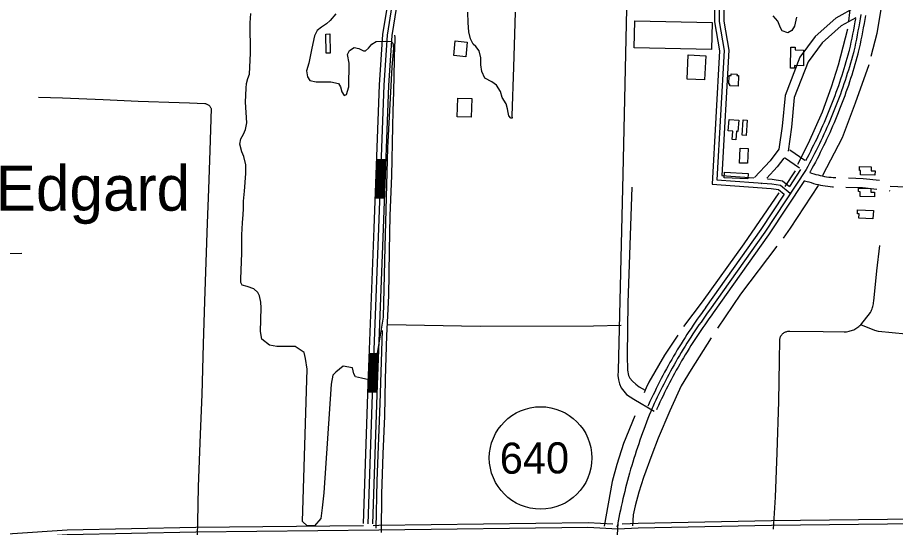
# Model space of a CAD drawing. Extents: x 3508733 to 3546731, y 546897 to 572481.
# Drawn here: x 3524246 to 3527070, y 560221 to 561862 of the extents above; entities that cross this region are included whole.
import ezdxf

# ---------------------------------------------------------------- set-up
doc = ezdxf.new("R2010")
doc.units = 0
for name, color, linetype in [('V-BLDG-OTLN', 7, 'Continuous'), ('V-DTCH-CNTR', 7, 'Continuous'), ('V-ROAD-CNTR', 7, 'Continuous'), ('V-ROAD-IDEN', 7, 'Continuous'), ('V-SITE-VEGE', 7, 'Continuous'), ('V-TOPO-GNAM-IDEN', 7, 'Continuous'), ('V-TOPO-SHOR', 7, 'Continuous')]:
    doc.layers.add(name, color=color, linetype=linetype)

msp = doc.modelspace()

# ---------------------------------------------------------------- linework, layer by layer
at = {"layer": 'V-BLDG-OTLN'}
for points in [[(3526478.2, 561760.1), (3526229.7, 561764.8), (3526231.4, 561851.6), (3526479.8, 561846.8)], [(3525250.2, 561809.5), (3525250.9, 561747.8), (3525238.4, 561747.7), (3525237.7, 561809.3)], [(3525688, 561736.2), (3525649, 561739.9), (3525653.5, 561787), (3525692.5, 561783.3)], [(3526732.8, 561699.1), (3526733.7, 561767.4), (3526747.8, 561767.2), (3526747.7, 561758.3), (3526774.4, 561757.9), (3526773.7, 561707.4), (3526745.4, 561707.7), (3526745.3, 561699)], [(3526399.4, 561664.1), (3526403, 561741.9), (3526459.7, 561739.2), (3526456.1, 561661.5)], [(3526533.9, 561648), (3526534.7, 561676), (3526541.6, 561675.8), (3526541.7, 561680.8), (3526560.2, 561680.3), (3526560.1, 561675.8), (3526564.5, 561675.6), (3526563.6, 561641.7), (3526536.9, 561642.4), (3526537, 561648)], [(3525706.9, 561601.4), (3525705.3, 561541.6), (3525660.4, 561542.8), (3525662, 561602.6)], [(3526558.8, 561496.2), (3526556.5, 561469.3), (3526544.3, 561470.3), (3526546.6, 561496.6), (3526532.2, 561497.9), (3526535.3, 561534.2), (3526565.7, 561531.6), (3526562.6, 561495.8)], [(3526592.8, 561532.5), (3526590, 561483), (3526576.8, 561483.8), (3526579.7, 561533.3)], [(3526596.2, 561441.1), (3526594.4, 561393.2), (3526568.1, 561394.2), (3526569.9, 561442.1)], [(3527003.9, 561355), (3526957, 561356.7), (3526957.5, 561370.5), (3526953.8, 561370.6), (3526954.3, 561382.9), (3526991.9, 561381.5), (3526991.4, 561369.1), (3527004.4, 561368.7)], [(3526595.2, 561343.2), (3526519.1, 561346.8), (3526519.9, 561364.5), (3526596.1, 561360.9)], [(3527002.2, 561285.3), (3526956, 561286.5), (3526956.4, 561301.9), (3526950.6, 561302), (3526951, 561313.6), (3526990.7, 561312.5), (3526990.3, 561300.2), (3527002.6, 561299.9)], [(3526997.6, 561214.8), (3526952.5, 561216.8), (3526953.1, 561230.4), (3526947.4, 561230.7), (3526947.9, 561243.4), (3526998.8, 561241.2)]]:
    msp.add_lwpolyline(points, close=True, dxfattribs=at)
at = {"layer": 'V-DTCH-CNTR'}
for points in [[(3525416.9, 560204.7), (3525418.1, 560327.9), (3525422.3, 560458.3), (3525426.9, 560579.6), (3525429.4, 560698.6), (3525434.2, 560839.5), (3525439.6, 560966.8), (3525442.3, 561111.1), (3525444, 561225.7), (3525449.4, 561353), (3525452.6, 561511.7), (3525453.9, 561561.2), (3525455.8, 561623.5), (3525458.1, 561727.1), (3525459.9, 561774.5), (3525460.2, 561782.4), (3525460.2, 561790.4), (3525460.1, 561798.3), (3525459.7, 561806.2)], [(3524313.3, 561605.7), (3524390.6, 561604.4), (3524521.4, 561598.3), (3524633.5, 561593.6), (3524765.9, 561589.1), (3524798.6, 561588)], [(3524798.6, 561588), (3524848.1, 561585.9), (3524850.4, 561585.5), (3524852.6, 561584.8), (3524854.7, 561584), (3524856.8, 561583), (3524858.8, 561581.8), (3524860.6, 561580.4), (3524862.3, 561578.9), (3524863.9, 561577.2), (3524865.3, 561575.4), (3524866.5, 561573.4), (3524867.6, 561571.4), (3524868.5, 561569.3), (3524863.8, 561435), (3524859.7, 561310.2), (3524855.5, 561201.1), (3524851.6, 561075.5), (3524847.3, 560949.5), (3524843.1, 560811.6), (3524838.3, 560649.5), (3524833.4, 560521.9), (3524826.8, 560352.2), (3524824.4, 560238.5), (3524823.2, 560195.8)], [(3527053.2, 561320.1), (3527227.7, 561312.6)], [(3526677.9, 560215.7), (3526684.1, 560319.2), (3526689.9, 560461.6), (3526694.9, 560626.2), (3526696.5, 560757.4), (3526698, 560825.7), (3526698.3, 560828.2), (3526698.8, 560830.6), (3526699.5, 560833), (3526700.4, 560835.3), (3526701.6, 560837.5), (3526702.8, 560839.6), (3526704.3, 560841.6), (3526705.9, 560843.5), (3526707.7, 560845.2), (3526709.6, 560846.8), (3526711.7, 560848.2), (3526713.8, 560849.4), (3526716, 560850.5), (3526718.4, 560851.3), (3526720.7, 560852), (3526723.2, 560852.5), (3526725.6, 560852.7), (3526728.1, 560852.8), (3526730.6, 560852.6), (3526837.4, 560851.5), (3526905, 560850.8), (3526908.9, 560851), (3526912.9, 560851.3), (3526916.8, 560851.9), (3526920.6, 560852.7), (3526924.5, 560853.6), (3526928.3, 560854.8), (3526932, 560856.2), (3526935.6, 560857.7), (3526939.2, 560859.5), (3526942.6, 560861.4), (3526946, 560863.5), (3526949.2, 560865.8), (3526952.3, 560868.3), (3526955.3, 560870.9), (3526958.1, 560873.7), (3526989.3, 560913.2), (3526991.3, 560916.9), (3526993.1, 560920.8), (3526994.7, 560924.8), (3526996.1, 560928.8), (3526997.3, 560932.9), (3526998.3, 560937.1), (3526999.1, 560941.3), (3526999.6, 560945.5), (3527000, 560949.8), (3527010.5, 561047), (3527019.2, 561129.1)], [(3523718.4, 561092.1), (3523864.6, 561096.1), (3524003.1, 561100.4), (3524146.8, 561101.7), (3524259.5, 561104.1)], [(3525435.7, 560874.7), (3525734, 560868.9), (3526098.5, 560870.7), (3526187, 560872.6)], [(3527252.9, 560831.6), (3527147.3, 560839.5), (3527015.7, 560851.8), (3527003.4, 560854.7), (3526958.1, 560873.7)]]:
    msp.add_lwpolyline(points, dxfattribs=at)
at = {"layer": 'V-ROAD-CNTR'}
for p, q in [((3525430.2, 561404.9), (3525400.3, 561406)), ((3527050, 561305.3), (3527051.5, 561305.2)), ((3525425.6, 561280), (3525395.6, 561281.1)), ((3525406.1, 560780.4), (3525376.1, 560781.6)), ((3525401.3, 560655.6), (3525371.3, 560656.5))]:
    msp.add_line(p, q, dxfattribs=at)
for points in [[(3526491.5, 562227.9), (3526487.7, 561848.4), (3526504.1, 561755.6), (3526479.9, 561326.3), (3526670.3, 561312.4), (3526693.8, 561308.9), (3526712.1, 561293.8)], [(3526506.5, 562227.8), (3526502.7, 561849.6), (3526519.2, 561756.5), (3526495.7, 561340.2), (3526671.9, 561327.3), (3526700.2, 561323.1), (3526731, 561297.6)], [(3526521.5, 562227.6), (3526517.7, 561850.9), (3526534.3, 561757.4), (3526511.5, 561354), (3526614.1, 561346.5)], [(3525482.3, 562076.1), (3525460.2, 561988.9), (3525435.3, 561905), (3525420.2, 561807.5), (3525409.2, 561645.6), (3525392, 561184.9), (3525372.2, 560681.9), (3525357.6, 560233.9)], [(3525496.9, 562072.4), (3525474.6, 561985), (3525449.9, 561901.7), (3525435.2, 561805.8), (3525424.1, 561644.8), (3525407, 561184.4), (3525387.1, 560681.4), (3525372.6, 560233.4)], [(3525511.4, 562068.8), (3525489.1, 561981), (3525464.6, 561898.4), (3525450.1, 561804.2), (3525439.1, 561644), (3525422, 561183.8), (3525402.1, 560680.8), (3525387.6, 560232.9)], [(3526206.2, 561939.5), (3526193.4, 561358.8), (3526177.8, 560724.9)], [(3526944, 561896.4), (3526877.9, 561860.9), (3526811.7, 561801.2), (3526762.1, 561734.8), (3526714.7, 561611.5), (3526705.7, 561513.1), (3526695.2, 561438.9), (3526666.7, 561400.7), (3526616.3, 561347.6)], [(3526942.1, 561861.3), (3526895.3, 561836.2), (3526834, 561780.9), (3526788.6, 561720.1), (3526744.2, 561604.7), (3526735.5, 561509.7), (3526724.7, 561432.8)], [(3526958.7, 561871.8), (3526956.5, 561858.7), (3526954.2, 561845.6), (3526951.8, 561832.5), (3526949.3, 561819.4), (3526946.8, 561806.3), (3526944.1, 561793.2), (3526941.4, 561780.2), (3526938.7, 561767.2), (3526935.8, 561754.2), (3526934.6, 561748.8)], [(3526973.5, 561869.3), (3526971.3, 561856.1), (3526968.9, 561842.9), (3526966.5, 561829.7), (3526964, 561816.5), (3526961.5, 561803.4), (3526958.8, 561790.2), (3526956.1, 561777.1), (3526953.3, 561764), (3526950.4, 561750.9), (3526949.2, 561745.5)], [(3526941.2, 561858.4), (3526939.4, 561848.2), (3526937, 561835.2), (3526934.6, 561822.2), (3526932.1, 561809.2), (3526929.4, 561796.2), (3526926.8, 561783.3), (3526924, 561770.4), (3526921.2, 561757.4), (3526920, 561752.1)], [(3526920.1, 561752.7), (3526917.1, 561741.6), (3526913.9, 561730.5), (3526910.7, 561719.5), (3526907.5, 561708.4), (3526904.1, 561697.4), (3526900.7, 561686.5), (3526897.2, 561675.5), (3526893.6, 561664.6), (3526890, 561653.7), (3526886.2, 561642.8), (3526882.4, 561631.9), (3526878.6, 561621.1), (3526874.6, 561610.3), (3526870.6, 561599.5), (3526866.5, 561588.8), (3526862.3, 561578), (3526858.1, 561567.3), (3526853.7, 561556.7), (3526849.3, 561546.1), (3526844.9, 561535.4), (3526840.3, 561524.9), (3526835.7, 561514.3), (3526831, 561503.8), (3526826.3, 561493.4), (3526821.4, 561482.9), (3526816.5, 561472.5), (3526811.6, 561462.1), (3526806.5, 561451.8), (3526801.4, 561441.5), (3526796.2, 561431.2), (3526790.9, 561421), (3526785.6, 561410.8), (3526780.4, 561401)], [(3526934.6, 561748.8), (3526931.5, 561737.6), (3526928.4, 561726.4), (3526925.1, 561715.3), (3526921.8, 561704.1), (3526918.5, 561693), (3526915, 561681.9), (3526911.5, 561670.9), (3526907.9, 561659.9), (3526904.2, 561648.8), (3526900.4, 561637.9), (3526896.6, 561626.9), (3526892.7, 561616), (3526888.7, 561605.1), (3526884.6, 561594.2), (3526880.5, 561583.4), (3526876.3, 561572.5), (3526872, 561561.8), (3526867.6, 561551), (3526863.2, 561540.3), (3526858.7, 561529.6), (3526854.1, 561518.9), (3526849.4, 561508.3), (3526844.7, 561497.7), (3526839.9, 561487.1), (3526835, 561476.6), (3526830.1, 561466.1), (3526825.1, 561455.6), (3526820, 561445.2), (3526814.8, 561434.8), (3526809.6, 561424.4), (3526804.3, 561414.1), (3526798.9, 561403.8), (3526793.4, 561393.6), (3526787.9, 561383.3), (3526782.5, 561373.4)], [(3526949.1, 561744.8), (3526946, 561733.6), (3526942.8, 561722.3), (3526939.5, 561711), (3526936.2, 561699.8), (3526932.8, 561688.6), (3526929.3, 561677.4), (3526925.7, 561666.3), (3526922.1, 561655.1), (3526918.4, 561644), (3526914.6, 561633), (3526910.7, 561621.9), (3526906.8, 561610.9), (3526902.7, 561599.9), (3526898.6, 561588.9), (3526894.5, 561578), (3526890.2, 561567.1), (3526885.9, 561556.2), (3526881.5, 561545.3), (3526877, 561534.5), (3526872.5, 561523.7), (3526867.8, 561512.9), (3526863.2, 561502.2), (3526858.4, 561491.5), (3526853.5, 561480.9), (3526848.6, 561470.2), (3526843.6, 561459.6), (3526838.6, 561449.1), (3526833.4, 561438.5), (3526828.2, 561428.1), (3526822.9, 561417.6), (3526817.6, 561407.2), (3526812.2, 561396.8), (3526806.7, 561386.5), (3526801.1, 561376.2), (3526795.6, 561366.2)], [(3526710.9, 561409.8), (3526689.6, 561381.4), (3526655.6, 561345.4)], [(3526761.4, 561377.8), (3526713.3, 561410.6)], [(3526778.3, 561402.6), (3526730.2, 561435.4)], [(3525403.3, 561405.9), (3525398.6, 561281)], [(3525406.2, 561405.8), (3525401.6, 561280.9)], [(3525409.2, 561405.7), (3525404.6, 561280.8)], [(3525412.2, 561405.6), (3525407.6, 561280.7)], [(3525415.2, 561405.5), (3525410.6, 561280.6)], [(3525418.2, 561405.4), (3525413.6, 561280.5)], [(3525421.2, 561405.3), (3525416.6, 561280.4)], [(3525424.2, 561405.2), (3525419.6, 561280.2)], [(3525427.2, 561405), (3525422.6, 561280.1)], [(3526782.5, 561373.4), (3526649.4, 561171.4), (3526471.6, 560920.4)], [(3526764.3, 561373.1), (3526728.7, 561319)], [(3526795, 561365.2), (3526793.7, 561363.2)], [(3526794, 561363.6), (3526800.2, 561362), (3526807.4, 561359.6), (3526814.1, 561357.5), (3526820.9, 561355.7), (3526827.7, 561354), (3526834.6, 561352.5), (3526841.6, 561351.2), (3526848.6, 561350.1), (3526855.6, 561349.1), (3526862.6, 561348.4), (3526869.7, 561347.8), (3526876.7, 561347.4), (3526878.5, 561347.3)], [(3526776.9, 561337.6), (3526661.8, 561162.9), (3526483.8, 560911.7)], [(3526639.5, 561328.5), (3526638.1, 561327)], [(3526657.8, 561343.4), (3526673.6, 561342.2), (3526706.5, 561337.3), (3526728.7, 561319)], [(3526776.6, 561337.3), (3526791.5, 561333.2), (3526798.3, 561331), (3526805.8, 561328.7), (3526813.4, 561326.6), (3526821, 561324.8), (3526828.7, 561323.1), (3526836.4, 561321.6), (3526844.2, 561320.4), (3526851.9, 561319.3), (3526859.8, 561318.5), (3526867.6, 561317.8), (3526870.6, 561317.7)], [(3526918.5, 561346.2), (3526965.5, 561344.9), (3527018.1, 561339.1)], [(3526910.5, 561316.4), (3526963.4, 561315), (3527010.2, 561309.8)], [(3526712.1, 561293.8), (3526637, 561179.8), (3526459.3, 560929)], [(3526459.5, 560929.3), (3526452.6, 560919.8), (3526445.7, 560910.3), (3526438.8, 560900.7), (3526432.1, 560891.1), (3526425.4, 560881.5), (3526418.7, 560871.8), (3526412.2, 560862), (3526405.7, 560852.2), (3526399.2, 560842.4), (3526392.9, 560832.5), (3526386.6, 560822.6), (3526380.3, 560812.6), (3526374.2, 560802.6), (3526368.1, 560792.5), (3526362.1, 560782.4), (3526356.1, 560772.3), (3526350.2, 560762.1), (3526344.4, 560751.9), (3526338.7, 560741.6), (3526333, 560731.3), (3526327.4, 560721), (3526321.9, 560710.6), (3526316.4, 560700.2), (3526311, 560689.8), (3526305.7, 560679.3), (3526300.4, 560668.8), (3526295.3, 560658.2), (3526290.2, 560647.6), (3526285.1, 560637), (3526280.2, 560626.3), (3526275.3, 560615.6), (3526273.6, 560611.8)], [(3526471.6, 560920.4), (3526464.7, 560911), (3526457.8, 560901.5), (3526451.1, 560892.1), (3526444.4, 560882.5), (3526437.7, 560873), (3526431.1, 560863.3), (3526424.6, 560853.7), (3526418.2, 560844), (3526411.8, 560834.2), (3526405.5, 560824.4), (3526399.3, 560814.6), (3526393.1, 560804.7), (3526387, 560794.8), (3526380.9, 560784.8), (3526375, 560774.8), (3526369.1, 560764.7), (3526363.2, 560754.6), (3526357.5, 560744.5), (3526351.8, 560734.3), (3526346.1, 560724.1), (3526340.6, 560713.9), (3526335.1, 560703.6), (3526329.7, 560693.3), (3526324.4, 560682.9), (3526319.1, 560672.5), (3526313.9, 560662.1), (3526308.8, 560651.6), (3526303.7, 560641.1), (3526298.7, 560630.6), (3526293.8, 560620), (3526289, 560609.4), (3526287.3, 560605.6)], [(3526483.7, 560911.5), (3526476.8, 560902.1), (3526470, 560892.8), (3526463.3, 560883.4), (3526456.7, 560873.9), (3526450.1, 560864.5), (3526443.6, 560854.9), (3526437.1, 560845.3), (3526430.7, 560835.7), (3526424.4, 560826), (3526418.1, 560816.3), (3526411.9, 560806.6), (3526405.8, 560796.8), (3526399.8, 560786.9), (3526393.8, 560777.1), (3526387.9, 560767.1), (3526382, 560757.2), (3526376.2, 560747.2), (3526370.5, 560737.1), (3526364.9, 560727.1), (3526359.3, 560716.9), (3526353.8, 560706.8), (3526348.4, 560696.6), (3526343, 560686.4), (3526337.7, 560676.1), (3526332.5, 560665.8), (3526327.3, 560655.5), (3526322.3, 560645.1), (3526317.2, 560634.7), (3526312.3, 560624.2), (3526307.4, 560613.8), (3526302.6, 560603.2), (3526300.9, 560599.5)], [(3525379.1, 560781.4), (3525375.2, 560681.8), (3525374.3, 560656.4)], [(3525382.1, 560781.3), (3525378.2, 560681.7), (3525377.3, 560656.3)], [(3525385.1, 560781.2), (3525381.1, 560681.6), (3525380.3, 560656.2)], [(3525388.1, 560781.1), (3525384.1, 560681.5), (3525383.3, 560656.1)], [(3525391.1, 560781), (3525387.1, 560681.4), (3525386.3, 560656.1)], [(3525394.1, 560780.8), (3525390.1, 560681.3), (3525389.3, 560656)], [(3525397.1, 560780.7), (3525393.1, 560681.1), (3525392.3, 560655.9)], [(3525400.1, 560780.6), (3525396.1, 560681), (3525395.3, 560655.8)], [(3525403.1, 560780.5), (3525399.1, 560680.9), (3525398.3, 560655.7)], [(3526228.6, 560634.6), (3526294.1, 560595)], [(3526287.3, 560605.6), (3526282.6, 560594.2), (3526278, 560582.8), (3526273.5, 560571.4), (3526269, 560559.9), (3526264.6, 560548.4), (3526260.3, 560536.9), (3526256.1, 560525.3), (3526252, 560513.7), (3526247.9, 560502.1), (3526243.9, 560490.5), (3526240, 560478.8), (3526236.1, 560467.2), (3526232.3, 560455.4), (3526228.6, 560443.7), (3526225, 560431.9), (3526221.5, 560420.2), (3526218, 560408.4), (3526214.6, 560396.5), (3526211.3, 560384.7), (3526208.1, 560372.8), (3526204.9, 560360.9), (3526201.8, 560349), (3526198.8, 560337.1), (3526195.9, 560325.1), (3526193, 560313.1), (3526190.3, 560301.2), (3526187.6, 560289.2), (3526185, 560277.1), (3526182.4, 560265.1), (3526180, 560253), (3526177.6, 560241), (3526175.3, 560228.9), (3526174, 560221.8)], [(3526287.3, 560605.6), (3526282.6, 560594.2), (3526278, 560582.8), (3526273.5, 560571.4), (3526269, 560559.9), (3526264.6, 560548.4), (3526260.3, 560536.9), (3526256.1, 560525.3), (3526252, 560513.7), (3526247.9, 560502.1), (3526243.9, 560490.5), (3526240, 560478.8), (3526236.1, 560467.2), (3526232.3, 560455.4), (3526228.6, 560443.7), (3526225, 560431.9), (3526221.5, 560420.2), (3526218, 560408.4), (3526214.6, 560396.5), (3526211.3, 560384.7), (3526208.1, 560372.8), (3526204.9, 560360.9), (3526201.8, 560349), (3526198.8, 560337.1), (3526195.9, 560325.1), (3526193, 560313.1), (3526190.3, 560301.2), (3526187.6, 560289.2), (3526185, 560277.1), (3526182.4, 560265.1), (3526176.4, 560235.7)], [(3526191.1, 560232.7), (3526242.2, 560235.1), (3526670.7, 560243.5), (3527231, 560250), (3527918, 560251.3), (3528397.7, 560253.8), (3528810.3, 560262.2), (3528855.9, 560258.6)], [(3523673.3, 560169.5), (3524230.3, 560187), (3524405.5, 560198.1), (3524819.6, 560207.5), (3525408, 560213.2), (3526080.6, 560222), (3526176.3, 560217), (3526242.7, 560220.1), (3526670.9, 560228.5), (3527231.1, 560235), (3527918, 560236.3), (3528397.9, 560238.8), (3528809.8, 560247.2), (3528869.9, 560242.5)], [(3523693.5, 560185.1), (3524229.6, 560202), (3524404.9, 560213.1), (3524819.4, 560222.5), (3525359, 560227.7)], [(3525389.7, 560228), (3525407.8, 560228.2), (3526080.9, 560237), (3526160.7, 560232.9)], [(3526176.4, 560235.7), (3526143.1, 559633.3), (3526116.2, 558886), (3526093.7, 558192.5), (3526073.8, 557590.5), (3526049.7, 556969.4)]]:
    msp.add_lwpolyline(points, dxfattribs=at)
msp.add_arc((3526262.4, 560713), 85.4, 172.0372, 246.7396, dxfattribs=at)
at = {"layer": 'V-ROAD-IDEN'}
msp.add_circle((3525928.4, 560444.9), 165, dxfattribs=at)
at = {"layer": 'V-SITE-VEGE'}
for points in [[(3525422.4, 560897.7), (3525390.6, 560711.2), (3525376, 560696.7), (3525351.8, 560701.5), (3525332.4, 560706.4), (3525327.5, 560716.1), (3525322.7, 560735.5), (3525293.6, 560740.3), (3525269.4, 560720.9), (3525259.7, 560711.2), (3525254.8, 560682.1), (3525230.6, 560332.9), (3525225.7, 560284.3), (3525220.9, 560250.4), (3525201.5, 560226.1), (3525177.3, 560226.1), (3525162.7, 560240.7), (3525177.3, 560730.6), (3525172.4, 560764.6), (3525167.6, 560784), (3525138.5, 560803.4), (3525080.3, 560803.4), (3525056.1, 560808.3), (3525031.8, 560827.7), (3525027, 560851.9), (3525029.4, 560928.5), (3525028.2, 560946.3), (3525024.3, 560966.9), (3525018.2, 560977.9), (3525006, 560989), (3524984.8, 560996.8), (3524968.4, 561001), (3524964.4, 561009.3), (3524964.5, 561020.3), (3524967.4, 561105.2), (3524967.3, 561163.4), (3524969.1, 561201.8), (3524971.4, 561228.5), (3524972.3, 561246.3), (3524972.5, 561271.7), (3524975.6, 561303.2), (3524979.6, 561360.7), (3524979.9, 561388.1), (3524973.3, 561414.9), (3524967.3, 561430.7), (3524960.7, 561454.7), (3524963.6, 561471.8), (3524972.7, 561486.8), (3524979, 561501.8), (3524983.3, 561523.7), (3524978.5, 561590.2), (3524981, 561635.4), (3524982.6, 561649.8), (3524986.8, 561666.2), (3524991.8, 561679.9), (3524995.2, 561747.7), (3524994.1, 561845.7), (3524995.8, 561875.1)], [(3525269.9, 561874.4), (3525251.2, 561853.3), (3525240.1, 561842.5), (3525223.6, 561831.7), (3525209.7, 561820.2), (3525200.7, 561803.2), (3525192.7, 561764.2), (3525182.6, 561715.6), (3525174.8, 561691), (3525178.1, 561671.8), (3525186.2, 561660.1), (3525206.7, 561655.8), (3525253.3, 561656), (3525277.9, 561650.2), (3525284.6, 561639.2), (3525288.6, 561623.4), (3525296.7, 561611.7), (3525303.6, 561614.3), (3525311.4, 561639.6), (3525312.8, 561715.7), (3525307, 561743.8), (3525313.3, 561756.8), (3525329.1, 561765.5), (3525344.1, 561762.6), (3525359.1, 561754.9), (3525365.3, 561755.6), (3525375, 561763.7), (3525385.4, 561776.6), (3525399.9, 561785.4), (3525430, 561786.4), (3525447.8, 561784.9), (3525453.3, 561780), (3525455.2, 561763.6), (3525449.8, 561702.6), (3525436.1, 561443.1), (3525427.4, 561124.5), (3525422.4, 560897.7)], [(3525846.9, 561879.9), (3525841, 561702.5), (3525836, 561545.6), (3525837.3, 561538.7), (3525832.5, 561538.1), (3525826.4, 561545.7), (3525824.5, 561556.7), (3525821.8, 561568.4), (3525817.2, 561584.9), (3525805.1, 561605.5), (3525799.1, 561624.8), (3525787, 561644.8), (3525771.3, 561655.2), (3525748.8, 561667.1), (3525739.5, 561689.1), (3525736.3, 561710.4), (3525735.8, 561732.3), (3525730.6, 561755), (3525720.4, 561768.8), (3525710.9, 561777.1), (3525702.9, 561793.7), (3525697.6, 561816.3), (3525695.8, 561845.8), (3525694.1, 561880.1)], [(3526751.3, 561864.1), (3526745.5, 561834.7), (3526736.5, 561820.4), (3526723.4, 561813), (3526705.6, 561819.4), (3526699.6, 561829.7), (3526691.6, 561850.3), (3526676.7, 561867.6)]]:
    msp.add_lwpolyline(points, dxfattribs=at)
at = {"layer": 'V-TOPO-SHOR'}
for p, q in [((3526747.4, 561369), (3526714.1, 561318.8)), ((3526245.1, 560673.9), (3526264.9, 560663.2))]:
    msp.add_line(p, q, dxfattribs=at)
for points in [[(3526943.4, 562025.1), (3526925.1, 561906.4), (3526919, 561851.1)], [(3527036.6, 561989.3), (3527029.2, 561929.3), (3527010.2, 561811.2), (3526991, 561736.9)], [(3526916, 561825.2), (3526885.5, 561709.3), (3526862.9, 561638.5), (3526834, 561557.5), (3526789.3, 561457.5), (3526754.4, 561389.5)], [(3526983.9, 561709.7), (3526940.3, 561587.1), (3526898.1, 561475.5), (3526835.4, 561353.8)], [(3526222.2, 561317), (3526215.5, 561129.5), (3526208.8, 560944), (3526207.1, 560774.9), (3526207.9, 560727), (3526211.2, 560710.5), (3526215.2, 560701.6), (3526224, 560691.9), (3526234.2, 560682.2), (3526245.1, 560673.9)], [(3526694.7, 561297.8), (3526581.7, 561133.6), (3526448.6, 560947.7), (3526388.3, 560867.7)], [(3526821.4, 561321.8), (3526731.2, 561184.7), (3526709, 561152.8)], [(3526688.2, 561126.4), (3526571.1, 560971.8), (3526496.9, 560863.2)], [(3525419.1, 560854.8), (3525411.2, 560620.3), (3525401.8, 560371.4), (3525398.2, 560218.5)], [(3526476.8, 560832), (3526412.2, 560730.1), (3526380.9, 560677.1), (3526343.9, 560596.2), (3526306.1, 560508.4), (3526285.7, 560455.3), (3526259, 560381.8), (3526244.2, 560334.8), (3526232.8, 560291.2), (3526226.3, 560261.9), (3526223.9, 560227)], [(3526370.3, 560840.6), (3526327.2, 560775.4), (3526276.5, 560688.4), (3526268.1, 560670.8), (3526264.9, 560663.2), (3526261.1, 560654.4)], [(3526231.6, 560580.9), (3526195.2, 560491.1), (3526173.3, 560423.7), (3526159.1, 560369.1), (3526133, 560225.9)]]:
    msp.add_lwpolyline(points, dxfattribs=at)

# ---------------------------------------------------------------- texts
at = {"layer": 'V-ROAD-IDEN'}
msp.add_text('640', height=100, rotation=0.3917, dxfattribs=at).set_placement((3525797.2, 560394))
at = {"layer": 'V-TOPO-GNAM-IDEN'}
msp.add_text('Edgard', height=145, dxfattribs=at).set_placement((3524175.6, 561240.8))

doc.saveas('drawing.dxf')
